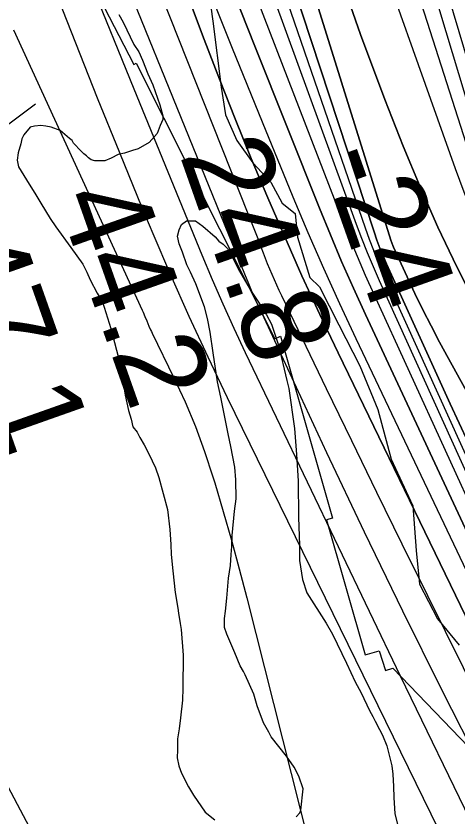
# Model space of a CAD drawing. Extents: x 3187622 to 3225504, y 800805 to 826213.
# Drawn here: x 3197378 to 3197716, y 819305 to 819917 of the extents above; entities that cross this region are included whole.
import ezdxf

# ---------------------------------------------------------------- set-up
doc = ezdxf.new("R2010")
doc.units = 0
for name, color, linetype in [('V-RIVR-EDGE', 7, 'Continuous'), ('V-RIVR-RANG', 7, 'Continuous'), ('V-RRAP-RVMT', 7, 'Continuous'), ('V-SITE-VEGE', 7, 'Continuous'), ('V-TOPO-DPTH', 7, 'Continuous'), ('V-TOPO-MAJR', 7, 'Continuous'), ('V-TOPO-MINR', 7, 'Continuous'), ('V-TOPO-SHOR', 7, 'Continuous'), ('V-TOPO-WATR', 7, 'Continuous')]:
    doc.layers.add(name, color=color, linetype=linetype)

msp = doc.modelspace()

# ---------------------------------------------------------------- linework, layer by layer
at = {"layer": 'V-RIVR-EDGE'}
msp.add_lwpolyline([(3197524.89, 819937.36), (3197528.31, 819913.44), (3197534.7, 819863), (3197538.13, 819841.69), (3197546.77, 819822.11), (3197558.9, 819805.13), (3197572.78, 819790.32), (3197581.43, 819774.21), (3197591.41, 819766.36), (3197593.1, 819748.1), (3197602.59, 819717.22), (3197609.96, 819710.24), (3197624.67, 819681.08), (3197640.67, 819649.75), (3197654.5, 819616.24), (3197664.84, 819578.4), (3197681.27, 819542.71), (3197683.79, 819508.37), (3197686.34, 819482.72), (3197700.18, 819456.17), (3197716.65, 819436.13)], dxfattribs=at)
at = {"layer": 'V-RRAP-RVMT'}
for p, q in [((3197420.63, 819971.99), (3197467.9, 819880.36)), ((3197467.9, 819880.36), (3197469.62, 819881.24)), ((3197469.62, 819881.24), (3197575.86, 819670.45)), ((3197575.86, 819670.45), (3197580.19, 819672.52)), ((3197580.19, 819672.52), (3197619.91, 819533.11)), ((3197619.91, 819533.11), (3197615.2, 819531.88)), ((3197615.2, 819531.88), (3197644.81, 819428.67)), ((3197644.81, 819428.67), (3197655.47, 819431.75)), ((3197655.47, 819431.75), (3197660.28, 819416.79)), ((3197660.28, 819416.79), (3197666.07, 819418.54)), ((3197666.07, 819418.54), (3197741.33, 819339.89))]:
    msp.add_line(p, q, dxfattribs=at)
at = {"layer": 'V-SITE-VEGE'}
for p, q in [((3197456.47, 819918.62), (3197459.76, 819912.59)), ((3197459.76, 819912.59), (3197468.01, 819895.69)), ((3197468.01, 819895.69), (3197471.7, 819890.06)), ((3197471.7, 819890.06), (3197474.59, 819883.62)), ((3197474.59, 819883.62), (3197478.73, 819873.15)), ((3197478.73, 819873.15), (3197482.45, 819864.7)), ((3197482.45, 819864.7), (3197487.85, 819849.39)), ((3197487.85, 819849.39), (3197489.95, 819840.92)), ((3197489.98, 819838.09), (3197488, 819833.62)), ((3197489.95, 819840.92), (3197489.98, 819838.09)), ((3197388.56, 819832.28), (3197383.77, 819826.57)), ((3197391.79, 819833.12), (3197388.56, 819832.28)), ((3197396.64, 819833.56), (3197391.79, 819833.12)), ((3197400.68, 819833.2), (3197396.64, 819833.56)), ((3197404.73, 819832.43), (3197400.68, 819833.2)), ((3197411.63, 819829.67), (3197404.73, 819832.43)), ((3197488, 819833.62), (3197485.63, 819827.53)), ((3197383.77, 819826.57), (3197382.18, 819823.32)), ((3197418.56, 819823.67), (3197411.63, 819829.67)), ((3197485.63, 819827.53), (3197479.63, 819820.6)), ((3197381.41, 819819.68), (3197379.45, 819812.79)), ((3197382.18, 819823.32), (3197381.41, 819819.68)), ((3197420.6, 819822.07), (3197418.56, 819823.67)), ((3197421.83, 819820.06), (3197420.6, 819822.07)), ((3197427.55, 819814.05), (3197421.83, 819820.06)), ((3197479.63, 819820.6), (3197471.19, 819815.67)), ((3197379.45, 819812.79), (3197378.7, 819807.12)), ((3197429.59, 819812.05), (3197427.55, 819814.05)), ((3197466.76, 819814.42), (3197460.71, 819812.34)), ((3197471.19, 819815.67), (3197466.76, 819814.42)), ((3197378.7, 819807.12), (3197379.55, 819801.87)), ((3197431.62, 819810.45), (3197429.59, 819812.05)), ((3197433.26, 819808.85), (3197431.62, 819810.45)), ((3197435.29, 819807.25), (3197433.26, 819808.85)), ((3197438.13, 819806.47), (3197435.29, 819807.25)), ((3197445.81, 819806.54), (3197438.13, 819806.47)), ((3197450.64, 819808.61), (3197445.81, 819806.54)), ((3197455.87, 819811.49), (3197450.64, 819808.61)), ((3197460.71, 819812.34), (3197455.87, 819811.49)), ((3197379.55, 819801.87), (3197387.77, 819788.61)), ((3197387.77, 819788.61), (3197392.27, 819781.78)), ((3197392.27, 819781.78), (3197396.8, 819774.14)), ((3197396.8, 819774.14), (3197403.78, 819762.48)), ((3197403.78, 819762.48), (3197408.29, 819756.06)), ((3197502.5, 819753.71), (3197504.48, 819757.78)), ((3197504.48, 819757.78), (3197508.1, 819760.64)), ((3197508.1, 819760.64), (3197514.97, 819760.71)), ((3197514.97, 819760.71), (3197520.66, 819756.71)), ((3197408.29, 819756.06), (3197419.75, 819740.4)), ((3197501.33, 819748.85), (3197502.5, 819753.71)), ((3197520.66, 819756.71), (3197530.04, 819748.32)), ((3197502.6, 819743.21), (3197501.33, 819748.85)), ((3197530.04, 819748.32), (3197532.9, 819745.11)), ((3197419.75, 819740.4), (3197428.77, 819727.55)), ((3197505.09, 819736.76), (3197502.6, 819743.21)), ((3197532.9, 819745.11), (3197536.16, 819742.71)), ((3197536.16, 819742.71), (3197539.42, 819739.51)), ((3197539.42, 819739.51), (3197543.12, 819733.08)), ((3197508.41, 819727.09), (3197505.09, 819736.76)), ((3197543.12, 819733.08), (3197548.06, 819723.42)), ((3197428.77, 819727.55), (3197432.06, 819721.52)), ((3197511.3, 819721.46), (3197508.41, 819727.09)), ((3197432.06, 819721.52), (3197434.54, 819715.48)), ((3197515.42, 819712.6), (3197511.3, 819721.46)), ((3197548.06, 819723.42), (3197557.52, 819706.94)), ((3197434.54, 819715.48), (3197439.89, 819705.42)), ((3197522.06, 819694.88), (3197515.42, 819712.6)), ((3197439.89, 819705.42), (3197444, 819698.59)), ((3197557.52, 819706.94), (3197562.85, 819699.31)), ((3197444, 819698.59), (3197450.25, 819678.43)), ((3197562.85, 819699.31), (3197569.41, 819688.86)), ((3197524.16, 819686), (3197522.06, 819694.88)), ((3197526.28, 819675.51), (3197524.16, 819686)), ((3197569.41, 819688.86), (3197573.12, 819681.61)), ((3197450.25, 819678.43), (3197457.39, 819651.01)), ((3197573.12, 819681.61), (3197578.53, 819665.49)), ((3197528.45, 819659.77), (3197526.28, 819675.51)), ((3197531.9, 819637.57), (3197528.45, 819659.77)), ((3197578.53, 819665.49), (3197584.85, 819638.47)), ((3197457.39, 819651.01), (3197459.04, 819647.39)), ((3197459.04, 819647.39), (3197458.66, 819644.15)), ((3197458.66, 819644.15), (3197459.96, 819634.86)), ((3197534.43, 819625.87), (3197531.9, 819637.57)), ((3197584.85, 819638.47), (3197586.52, 819632.42)), ((3197459.96, 819634.86), (3197461.25, 819627.2)), ((3197586.52, 819632.42), (3197590.85, 819601.74)), ((3197461.25, 819627.2), (3197463.78, 819615.49)), ((3197539.96, 819597.62), (3197534.43, 819625.87)), ((3197463.78, 819615.49), (3197465.87, 819609.05)), ((3197465.87, 819609.05), (3197467.14, 819603)), ((3197467.14, 819603), (3197470.41, 819598.98)), ((3197470.41, 819598.98), (3197472.47, 819594.96)), ((3197590.85, 819601.74), (3197592.25, 819581.94)), ((3197472.47, 819594.96), (3197475.76, 819589.33)), ((3197542.07, 819587.94), (3197539.96, 819597.62)), ((3197475.76, 819589.33), (3197479.46, 819582.5)), ((3197545.04, 819572.2), (3197542.07, 819587.94)), ((3197479.46, 819582.5), (3197484.41, 819571.63)), ((3197592.25, 819581.94), (3197593.66, 819561.74)), ((3197484.41, 819571.63), (3197486.91, 819564.37)), ((3197545.95, 819562.51), (3197545.04, 819572.2)), ((3197486.91, 819564.37), (3197493.61, 819539.78)), ((3197546.08, 819547.95), (3197545.95, 819562.51)), ((3197593.66, 819561.74), (3197593.92, 819533.85)), ((3197544.96, 819538.64), (3197546.08, 819547.95)), ((3197493.61, 819539.78), (3197495.37, 819524.43)), ((3197543.12, 819520.03), (3197544.96, 819538.64)), ((3197593.92, 819533.85), (3197594.53, 819512.44)), ((3197495.37, 819524.43), (3197496.29, 819513.12)), ((3197542.79, 819511.54), (3197543.12, 819520.03)), ((3197496.29, 819513.12), (3197496.36, 819505.44)), ((3197594.53, 819512.44), (3197594.64, 819500.71)), ((3197542.44, 819505.47), (3197542.79, 819511.54)), ((3197496.36, 819505.44), (3197497.69, 819492.92)), ((3197541.71, 819496.98), (3197542.44, 819505.47)), ((3197594.64, 819500.71), (3197596.8, 819486.18)), ((3197540.95, 819492.12), (3197541.71, 819496.98)), ((3197497.69, 819492.92), (3197499.46, 819476.36)), ((3197540.19, 819487.26), (3197540.95, 819492.12)), ((3197539.12, 819471.89), (3197540.19, 819487.26)), ((3197596.8, 819486.18), (3197600.12, 819476.1)), ((3197499.46, 819476.36), (3197501.6, 819464.26)), ((3197600.12, 819476.1), (3197614.9, 819452.79)), ((3197538, 819462.18), (3197539.12, 819471.89)), ((3197501.6, 819464.26), (3197502.04, 819460.62)), ((3197502.04, 819460.62), (3197503.33, 819452.55)), ((3197537.25, 819456.51), (3197538, 819462.18)), ((3197503.33, 819452.55), (3197504.18, 819448.11)), ((3197537.31, 819449.64), (3197537.25, 819456.51)), ((3197614.9, 819452.79), (3197619.83, 819444.35)), ((3197504.18, 819448.11), (3197505.58, 819428.31)), ((3197538.98, 819444.4), (3197537.31, 819449.64)), ((3197545.18, 819430.3), (3197538.98, 819444.4)), ((3197619.83, 819444.35), (3197630.55, 819422.22)), ((3197505.58, 819428.31), (3197505.41, 819403.25)), ((3197549.31, 819420.24), (3197545.18, 819430.3)), ((3197630.55, 819422.22), (3197637.15, 819408.13)), ((3197551.78, 819415.82), (3197549.31, 819420.24)), ((3197553.02, 819413.4), (3197551.78, 819415.82)), ((3197559.62, 819398.51), (3197553.02, 819413.4)), ((3197505.41, 819403.25), (3197505.09, 819393.95)), ((3197637.15, 819408.13), (3197641.68, 819399.69)), ((3197562.14, 819389.64), (3197559.62, 819398.51)), ((3197641.68, 819399.69), (3197648.28, 819386.01)), ((3197505.09, 819393.95), (3197503.6, 819380.59)), ((3197567.11, 819376.75), (3197562.14, 819389.64)), ((3197648.28, 819386.01), (3197650.74, 819381.58)), ((3197503.6, 819380.59), (3197502.47, 819372.09)), ((3197650.74, 819381.58), (3197652.4, 819377.96)), ((3197652.4, 819377.96), (3197655.69, 819371.52)), ((3197502.47, 819372.09), (3197501.33, 819364.4)), ((3197571.22, 819369.51), (3197567.11, 819376.75)), ((3197655.69, 819371.52), (3197658.16, 819367.1)), ((3197572.87, 819365.89), (3197571.22, 819369.51)), ((3197584.73, 819351.04), (3197572.87, 819365.89)), ((3197658.16, 819367.1), (3197661.47, 819359.04)), ((3197501.33, 819364.4), (3197501.41, 819355.91)), ((3197501.41, 819355.91), (3197501.06, 819349.84)), ((3197661.47, 819359.04), (3197665.25, 819343.72)), ((3197501.06, 819349.84), (3197502.33, 819343.79)), ((3197590.47, 819342.61), (3197584.73, 819351.04)), ((3197502.33, 819343.79), (3197504.41, 819338.15)), ((3197594.18, 819335.77), (3197590.47, 819342.61)), ((3197665.25, 819343.72), (3197666.12, 819337.26)), ((3197504.41, 819338.15), (3197509.76, 819327.69)), ((3197597.5, 819326.1), (3197594.18, 819335.77)), ((3197666.12, 819337.26), (3197666.61, 819327.96)), ((3197509.76, 819327.69), (3197513.46, 819321.26)), ((3197595.63, 819309.91), (3197597.5, 819326.1)), ((3197666.61, 819327.96), (3197666.69, 819319.47)), ((3197513.46, 819321.26), (3197522.48, 819308.41)), ((3197666.69, 819319.47), (3197667.62, 819306.95)), ((3197522.48, 819308.41), (3197529.81, 819302.42)), ((3197592.04, 819304.62), (3197594.84, 819307.88)), ((3197594.84, 819307.88), (3197595.63, 819309.91)), ((3197667.62, 819306.95), (3197672.24, 819288.81))]:
    msp.add_line(p, q, dxfattribs=at)
at = {"layer": 'V-TOPO-DPTH'}
for points in [[(3198081.41, 819086.53), (3198031.77, 819158.23), (3197984.16, 819231.2), (3197939.59, 819306.07), (3197897.04, 819382.2), (3197730.37, 819695.43), (3197715.03, 819725.47), (3197700.39, 819755.83), (3197686.8, 819786.66), (3197673.89, 819817.82), (3197659.78, 819853.6), (3197641.23, 819903.17), (3197623.85, 819953.14), (3197608.24, 820003.68), (3197593.82, 820054.61), (3197385.39, 820842.97)], [(3197385.39, 820842.97), (3197593.82, 820054.61), (3197608.24, 820003.68), (3197623.85, 819953.14), (3197641.23, 819903.17), (3197659.78, 819853.6), (3197673.89, 819817.82), (3197686.8, 819786.66), (3197700.39, 819755.83), (3197715.03, 819725.47), (3197730.37, 819695.43), (3197897.04, 819382.2), (3197939.59, 819306.07), (3197984.16, 819231.2), (3198031.77, 819158.23), (3198081.41, 819086.53)], [(3198035.2, 819089.5), (3197991.7, 819162.41), (3197948.67, 819235.62), (3197808.68, 819476.5), (3197788.13, 819512.2), (3197767.78, 819548.01), (3197747.73, 819583.98), (3197727.87, 819620.07), (3197701.8, 819667.93), (3197695.26, 819680.24), (3197688.91, 819692.64), (3197682.83, 819705.17), (3197676.94, 819717.79), (3197666.56, 819740.63), (3197666.01, 819741.91), (3197664.58, 819745.84), (3197589.13, 819987.8), (3197552.26, 820110.46), (3197517.07, 820233.58), (3197484.4, 820357.4), (3197453.41, 820481.67), (3197371.82, 820823.76)], [(3197371.82, 820823.76), (3197453.41, 820481.67), (3197484.4, 820357.4), (3197517.07, 820233.58), (3197552.26, 820110.46), (3197589.13, 819987.8), (3197664.58, 819745.84), (3197666.01, 819741.91), (3197666.56, 819740.63), (3197676.94, 819717.79), (3197682.83, 819705.17), (3197688.91, 819692.64), (3197695.26, 819680.24), (3197701.8, 819667.93), (3197727.87, 819620.07), (3197747.73, 819583.98), (3197767.78, 819548.01), (3197788.13, 819512.2), (3197808.68, 819476.5), (3197948.67, 819235.62), (3197991.7, 819162.41), (3198035.2, 819089.5)], [(3197285.44, 820823.43), (3197357.1, 820581.11), (3197399.5, 820442.49), (3197443.61, 820304.44), (3197490.29, 820167.23), (3197538.67, 820030.59), (3197637.97, 819758.24), (3197642.1, 819747.3), (3197646.4, 819736.42), (3197650.93, 819725.64), (3197655.64, 819714.92), (3197745.2, 819516.93), (3197796.25, 819408), (3197849.22, 819300.05), (3197905.07, 819193.56), (3197962.83, 819088.03), (3198136.17, 818781.25)], [(3197285.44, 820823.43), (3197357.1, 820581.11), (3197399.5, 820442.49), (3197443.61, 820304.44), (3197490.29, 820167.23), (3197538.67, 820030.59), (3197637.97, 819758.24), (3197642.1, 819747.3), (3197646.4, 819736.42), (3197650.93, 819725.64), (3197655.64, 819714.92), (3197745.2, 819516.93), (3197796.25, 819408), (3197849.22, 819300.05), (3197905.07, 819193.56), (3197962.83, 819088.03), (3198136.17, 818781.25)], [(3198048.82, 818988.41), (3198034.41, 819014.08), (3197827.26, 819387.33), (3197796.24, 819444.84), (3197766.17, 819502.83), (3197737.49, 819561.52), (3197709.76, 819620.68), (3197661.12, 819727.78), (3197658.51, 819733.79), (3197656.03, 819739.84), (3197653.75, 819745.97), (3197651.61, 819752.16), (3197411.32, 820482.84), (3197390.99, 820545.85), (3197371.15, 820609.01), (3197352.02, 820672.38)], [(3197352.02, 820672.38), (3197371.15, 820609.01), (3197390.99, 820545.85), (3197411.32, 820482.84), (3197651.61, 819752.16), (3197653.75, 819745.97), (3197656.03, 819739.84), (3197658.51, 819733.79), (3197661.12, 819727.78), (3197709.76, 819620.68), (3197737.49, 819561.52), (3197766.17, 819502.83), (3197796.24, 819444.84), (3197827.26, 819387.33), (3198034.41, 819014.08), (3198048.82, 818988.41)], [(3198087.35, 818795.7), (3198024.69, 818907.23), (3197981.71, 818985.8), (3197939.92, 819065), (3197899.93, 819145.11), (3197861.14, 819225.85), (3197645.02, 819689.03), (3197635.82, 819709.2), (3197626.85, 819729.47), (3197618.23, 819749.89), (3197609.84, 819770.42), (3197560.46, 819894.28), (3197527.81, 819976.9), (3197495.49, 820059.66), (3197463.67, 820142.6), (3197432.18, 820225.68), (3197318.81, 820527.48), (3197305.83, 820561.81), (3197292.75, 820596.1), (3197279.51, 820630.33), (3197266.18, 820664.53)], [(3197266.18, 820664.53), (3197279.51, 820630.33), (3197292.75, 820596.1), (3197305.83, 820561.81), (3197318.81, 820527.48), (3197432.18, 820225.68), (3197463.67, 820142.6), (3197495.49, 820059.66), (3197527.81, 819976.9), (3197560.46, 819894.28), (3197609.84, 819770.42), (3197618.23, 819749.89), (3197626.85, 819729.47), (3197635.82, 819709.2), (3197645.02, 819689.03), (3197861.14, 819225.85), (3197899.93, 819145.11), (3197939.92, 819065), (3197981.71, 818985.8), (3198024.69, 818907.23), (3198087.35, 818795.7)], [(3198037.18, 818806.56), (3198029.73, 818821.68), (3197624.2, 819659.66), (3197610.22, 819689.11), (3197596.52, 819718.69), (3197583.27, 819748.48), (3197570.3, 819778.39), (3197557.74, 819808.48), (3197545.43, 819838.67), (3197533.48, 819869), (3197521.77, 819899.43), (3197508.9, 819933.53), (3197490.83, 819981.04), (3197472.61, 820028.49), (3197454.17, 820075.86), (3197435.58, 820123.17), (3197372.67, 820282.2), (3197337.72, 820374.15), (3197304.42, 820466.68), (3197273.63, 820560.07), (3197244.5, 820654.03)]]:
    msp.add_lwpolyline(points, dxfattribs=at)
at = {"layer": 'V-TOPO-MAJR'}
for points in [[(3197394.12, 820856.36), (3197486.48, 820505.12), (3197521.06, 820380.08), (3197557.73, 820255.69), (3197597.55, 820132.27), (3197639.46, 820009.5), (3197713.69, 819800.75), (3197720.36, 819782.96), (3197727.43, 819765.35), (3197735.11, 819747.99), (3197743.19, 819730.79), (3197869.96, 819472.66), (3197903.53, 819408.31), (3197939.12, 819345.16), (3197977.73, 819283.81), (3198018.36, 819223.67), (3198067.53, 819154.58)], [(3197169.42, 820662.33), (3197339.43, 820193.69), (3197370.31, 820110.2), (3197401.88, 820026.96), (3197434.48, 819944.13), (3197467.77, 819861.56), (3197519.87, 819734.61), (3197527.79, 819715.79), (3197535.92, 819697.07), (3197544.37, 819678.49), (3197553.04, 819660.01), (3197671.61, 819412.71), (3197729.11, 819294.29), (3197787.4, 819176.27), (3197846.87, 819058.84), (3197907.13, 818941.8), (3198007.95, 818748.35), (3198018.49, 818728.39), (3198029.19, 818708.51), (3198040.12, 818688.76)]]:
    msp.add_lwpolyline(points, dxfattribs=at)
at = {"layer": 'V-TOPO-MINR'}
for points in [[(3197485.11, 820863.46), (3197602.19, 820337.02), (3197624.27, 820242.5), (3197647.68, 820148.31), (3197673.09, 820054.65), (3197699.83, 819961.33), (3197753.2, 819782.28), (3197754.33, 819778.78), (3197755.58, 819775.32), (3197756.98, 819771.93), (3197758.5, 819768.58), (3197783.22, 819717.27), (3197791.47, 819701.06), (3197800.18, 819685.13), (3197809.6, 819669.6), (3197819.48, 819654.33), (3197829.73, 819639.28), (3197840, 819624.25), (3197850.31, 819609.24), (3197860.65, 819594.26), (3197945.01, 819472.24), (3197997.19, 819396.02), (3198048.87, 819319.47)], [(3197385.39, 820842.97), (3197593.82, 820054.61), (3197608.24, 820003.68), (3197623.85, 819953.14), (3197641.23, 819903.17), (3197659.78, 819853.6), (3197673.89, 819817.82), (3197686.8, 819786.66), (3197700.39, 819755.83), (3197715.03, 819725.47), (3197730.37, 819695.43), (3197897.04, 819382.2), (3197939.59, 819306.07), (3197984.16, 819231.2), (3198031.77, 819158.23), (3198081.41, 819086.53)], [(3197371.82, 820823.76), (3197453.41, 820481.67), (3197484.4, 820357.4), (3197517.07, 820233.58), (3197552.26, 820110.46), (3197589.13, 819987.8), (3197664.58, 819745.84), (3197666.01, 819741.91), (3197666.56, 819740.63), (3197676.94, 819717.79), (3197682.83, 819705.17), (3197688.91, 819692.64), (3197695.26, 819680.24), (3197701.8, 819667.93), (3197727.87, 819620.07), (3197747.73, 819583.98), (3197767.78, 819548.01), (3197788.13, 819512.2), (3197808.68, 819476.5), (3197948.67, 819235.62), (3197991.7, 819162.41), (3198035.2, 819089.5)], [(3197285.44, 820823.43), (3197357.1, 820581.11), (3197399.5, 820442.49), (3197443.61, 820304.44), (3197490.29, 820167.23), (3197538.67, 820030.59), (3197637.97, 819758.24), (3197642.1, 819747.3), (3197646.4, 819736.42), (3197650.93, 819725.64), (3197655.64, 819714.92), (3197745.2, 819516.93), (3197796.25, 819408), (3197849.22, 819300.05), (3197905.07, 819193.56), (3197962.83, 819088.03), (3198136.17, 818781.25)], [(3197101.67, 820805.66), (3197148.44, 820639.25), (3197175.94, 820547.4), (3197205.48, 820456.26), (3197238.09, 820366.16), (3197272.74, 820276.77), (3197301.38, 820206.46), (3197324.96, 820148.05), (3197348.31, 820089.55), (3197371.3, 820030.91), (3197394.07, 819972.17), (3197406.77, 819939.1), (3197423.18, 819896.9), (3197439.84, 819854.8), (3197456.85, 819812.85), (3197474.11, 819770.99), (3197482.46, 819750.98), (3197496, 819719.33), (3197509.91, 819687.84), (3197524.39, 819656.61), (3197539.23, 819625.55), (3197844.87, 819000.56), (3197870.23, 818949.23)], [(3197277.79, 820810.78), (3197401.73, 820396.89), (3197436.71, 820284.8), (3197473.4, 820173.3), (3197512.67, 820062.68), (3197553.64, 819952.65), (3197626.76, 819763.05), (3197632.6, 819748.31), (3197638.61, 819733.65), (3197644.89, 819719.1), (3197651.35, 819704.62), (3197787.76, 819406.19), (3197839.85, 819296), (3197893.8, 819186.76), (3197950.54, 819078.95), (3198009.15, 818972.08), (3198113.19, 818788)], [(3197172.15, 820777.18), (3197284.37, 820430.79), (3197325.56, 820308.2), (3197368.49, 820186.24), (3197414.05, 820065.24), (3197461.36, 819944.88), (3197552.51, 819720.11), (3197555.61, 819712.63), (3197558.79, 819705.19), (3197562.08, 819697.79), (3197565.45, 819690.43), (3197615.39, 819583.45), (3197644.13, 819522.79), (3197673.32, 819462.35), (3197703.2, 819402.24), (3197733.53, 819342.36), (3198044.81, 818736.38)], [(3197466.59, 820701.72), (3197742.08, 819787.87), (3197744.62, 819780.1), (3197747.41, 819772.42), (3197750.54, 819764.88), (3197753.92, 819757.43), (3197810.73, 819639.5), (3197828.15, 819605.37), (3197846.6, 819571.85), (3197866.59, 819539.21), (3197887.6, 819507.17), (3197909.42, 819475.61), (3197931.29, 819444.08), (3197953.23, 819412.6), (3197975.22, 819381.15), (3198011.33, 819329.65), (3198050.84, 819272.1)], [(3197352.02, 820672.38), (3197371.15, 820609.01), (3197390.99, 820545.85), (3197411.32, 820482.84), (3197651.61, 819752.16), (3197653.75, 819745.97), (3197656.03, 819739.84), (3197658.51, 819733.79), (3197661.12, 819727.78), (3197709.76, 819620.68), (3197737.49, 819561.52), (3197766.17, 819502.83), (3197796.24, 819444.84), (3197827.26, 819387.33), (3198034.41, 819014.08), (3198048.82, 818988.41)], [(3197252.48, 820660.72), (3197272.48, 820599.98), (3197294.08, 820539.78), (3197316.74, 820479.95), (3197326.88, 820454.24), (3197355.24, 820381.76), (3197383.39, 820309.2), (3197411.21, 820236.51), (3197438.81, 820163.74), (3197476.93, 820062.53), (3197498.59, 820005.8), (3197520.59, 819949.2), (3197543.11, 819892.8), (3197565.96, 819836.53), (3197589.61, 819779.05), (3197601.11, 819751.72), (3197612.9, 819724.52), (3197625.13, 819697.51), (3197637.65, 819670.64), (3197941.36, 819032.03), (3197965.34, 818982.82), (3197989.92, 818933.92), (3198015.41, 818885.48), (3198041.5, 818837.36)], [(3197244.5, 820654.03), (3197273.63, 820560.07), (3197304.42, 820466.68), (3197337.72, 820374.15), (3197372.67, 820282.2), (3197435.58, 820123.17), (3197454.17, 820075.86), (3197472.61, 820028.49), (3197490.83, 819981.04), (3197508.9, 819933.53), (3197521.77, 819899.43), (3197533.48, 819869), (3197545.43, 819838.67), (3197557.74, 819808.48), (3197570.3, 819778.39), (3197583.27, 819748.48), (3197596.52, 819718.69), (3197610.22, 819689.11), (3197624.2, 819659.66), (3198029.73, 818821.68), (3198037.18, 818806.56)], [(3197346.23, 820654.15), (3197377.16, 820550.87), (3197409.08, 820447.9), (3197442.47, 820345.4), (3197476.85, 820243.21), (3197644.9, 819755.24), (3197647.99, 819746.66), (3197651.24, 819738.14), (3197654.74, 819729.72), (3197658.39, 819721.36), (3197726.54, 819571.19), (3197765.43, 819488.32), (3197805.71, 819406.15), (3197848.06, 819325.03), (3197891.8, 819244.61), (3198154.57, 818775.85)], [(3197459.76, 820654.68), (3197480.79, 820580.05), (3197503.04, 820505.76), (3197526.09, 820431.72), (3197730.57, 819793.35), (3197734.69, 819781.35), (3197739.14, 819769.49), (3197744.07, 819757.82), (3197749.34, 819746.28), (3197840.05, 819557.97), (3197865.73, 819507.81), (3197893, 819458.56), (3197922.62, 819410.7), (3197953.82, 819363.76), (3197962.22, 819351.77), (3197990.45, 819311.56), (3198018.75, 819271.38), (3198047.14, 819231.27)], [(3197428.77, 820084.51), (3197555.17, 819766.23), (3197557.68, 819759.88), (3197560.16, 819753.51), (3197562.62, 819747.14), (3197565.05, 819740.76), (3197566.74, 819736.31), (3197568.34, 819732.16), (3197569.98, 819728.02), (3197571.68, 819723.91), (3197573.41, 819719.81), (3197575.19, 819715.74), (3197577.01, 819711.68), (3197578.88, 819707.64), (3197580.79, 819703.62), (3197615.13, 819632.29), (3197634.3, 819592.65), (3197653.56, 819553.06), (3197672.95, 819513.53), (3197692.43, 819474.04), (3198060.37, 818731.31)], [(3197375.73, 819906.81), (3197474.37, 819692.24), (3197475.07, 819690.69), (3197476.41, 819687.56), (3197477.77, 819684.19), (3197479.48, 819680.07), (3197480.67, 819677.34), (3197481.3, 819675.99), (3197481.94, 819674.64), (3197498.53, 819640.62), (3197507.04, 819622.09), (3197514.94, 819603.33), (3197521.95, 819584.21), (3197528.36, 819564.86), (3197529.78, 819560.22), (3197536.29, 819538.33), (3197542.58, 819516.38), (3197548.56, 819494.34), (3197554.32, 819472.25), (3197615.62, 819229.86)], [(3197614.75, 818955.79), (3197561.15, 819017.52), (3197530.14, 819055.83), (3197500.97, 819095.4), (3197474.58, 819136.87), (3197450.04, 819179.62), (3197262.07, 819534.74), (3197247.95, 819562.08), (3197234.2, 819589.6), (3197221, 819617.4), (3197208.18, 819645.37), (3197179.11, 819710.51), (3197165.9, 819740.03), (3197152.65, 819769.53), (3197139.32, 819798.99), (3197125.95, 819828.44), (3197099.15, 819887.31)]]:
    msp.add_lwpolyline(points, dxfattribs=at)
at = {"layer": 'V-TOPO-SHOR'}
msp.add_lwpolyline([(3197392.69, 819850.05), (3197335.03, 819806.94), (3197309.45, 819789.87), (3197299.93, 819784.83), (3197265.79, 819766.69), (3197247.39, 819758.6), (3197220.11, 819747.79), (3197203.68, 819740.04), (3197190.23, 819732.98), (3197173.48, 819724.25), (3197158.71, 819716.52), (3197145.22, 819712.43), (3197132.37, 819710), (3197116.57, 819706.23), (3197104.72, 819703.47), (3197090.56, 819701.03), (3197069.69, 819709.08), (3197048.5, 819717.46), (3197028.96, 819725.19)], dxfattribs=at)
at = {"layer": 'V-TOPO-WATR'}
msp.add_lwpolyline([(3197266.18, 820664.53), (3197279.51, 820630.33), (3197292.75, 820596.1), (3197305.83, 820561.81), (3197318.81, 820527.48), (3197432.18, 820225.68), (3197463.67, 820142.6), (3197495.49, 820059.66), (3197527.81, 819976.9), (3197560.46, 819894.28), (3197609.84, 819770.42), (3197618.23, 819749.89), (3197626.85, 819729.47), (3197635.82, 819709.2), (3197645.02, 819689.03), (3197861.14, 819225.85), (3197899.93, 819145.11), (3197939.92, 819065), (3197981.71, 818985.8), (3198024.69, 818907.23), (3198087.35, 818795.7)], dxfattribs=at)

# ---------------------------------------------------------------- texts
at = {"layer": 'V-RIVR-RANG'}
for s, rotation, p in [('24.8', 289.47833, (3197502.68, 819811.27)), ('-24', 289.55075, (3197609.29, 819809.46)), ('44.2', 289.47833, (3197408.49, 819777.7)), ('47.1', 289.47833, (3197315.09, 819741.89))]:
    msp.add_text(s, height=67, rotation=rotation, dxfattribs=at).set_placement(p)

doc.saveas('drawing.dxf')
